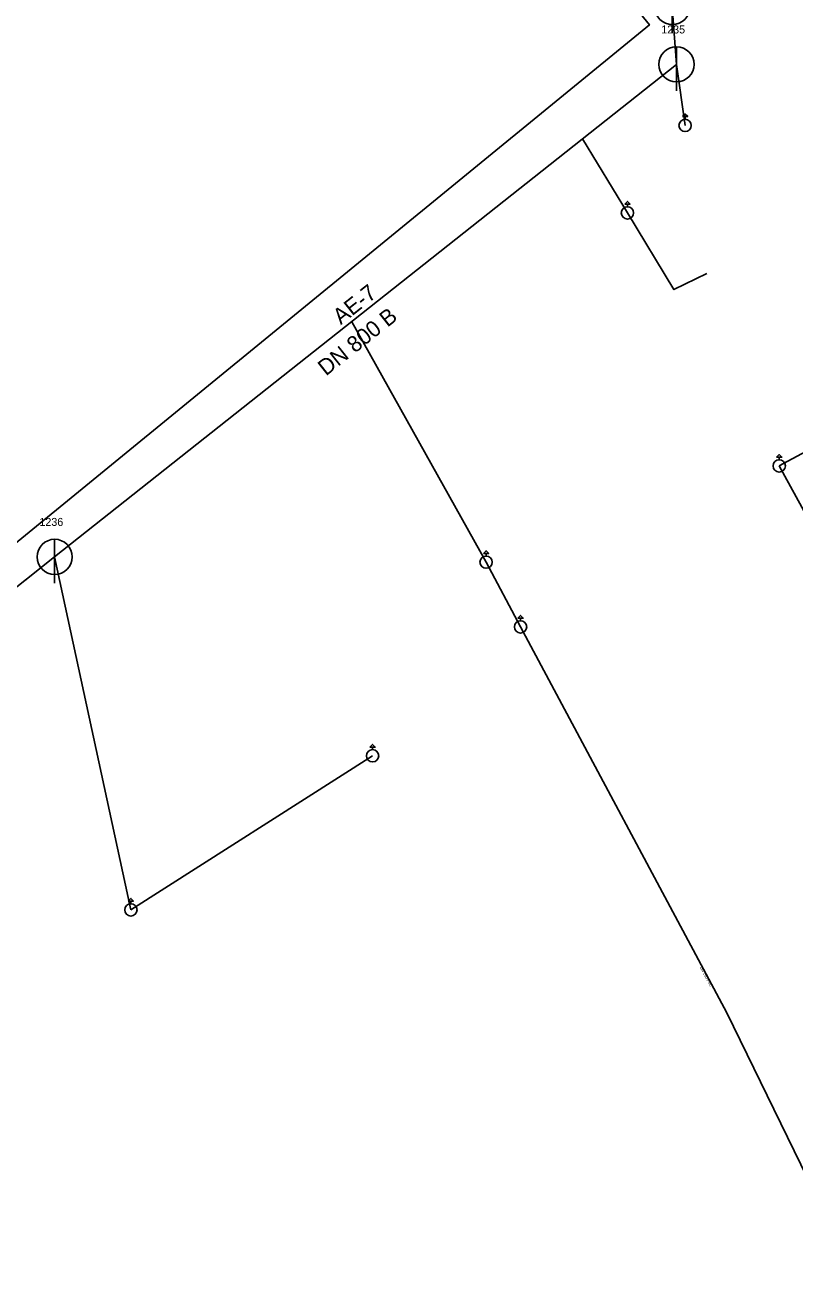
# Model space of a CAD drawing. Extents: x -493753 to -49291, y -1127285 to -112662.
# Drawn here: x -492986.6 to -492942.9, y -1126707.8 to -1126636.7 of the extents above; entities that cross this region are included whole.
import ezdxf

# ---------------------------------------------------------------- set-up
doc = ezdxf.new("R2010")
doc.units = 0
for name, color, linetype in [('Vrstva 1', 7, 'Continuous'), ('Vrstva 15', 7, 'Continuous'), ('Vrstva 17', 7, 'Continuous'), ('Vrstva 19', 7, 'Continuous')]:
    doc.layers.add(name, color=color, linetype=linetype)

# ---------------------------------------------------------------- blocks, each defined once
blk = doc.blocks.new('_SACHT')
at = {"layer": 'Vrstva 1'}
blk.add_line((0, 0.035), (0, 0.05), dxfattribs=at)
blk.add_lwpolyline([(-0.015, 0.05), (0, 0.065), (0.015, 0.05), (0.0025, 0.05)], close=True, dxfattribs=at)
blk.add_circle((0, 0), 0.035, dxfattribs=at)
blk = doc.blocks.new('_SACH0')
at = {"layer": 'Vrstva 1'}
blk.add_line((0, 0.05), (0, -0.075), dxfattribs=at)
blk.add_circle((0, 0), 0.05, dxfattribs=at)

msp = doc.modelspace()

# ---------------------------------------------------------------- linework, layer by layer
at = {"layer": 'Vrstva 15'}
for p, q in [((-492949.6, -1126638.98), (-492949.84, -1126635.71)), ((-492984.94, -1126666.98), (-492949.6, -1126638.98)), ((-492949.11, -1126642.45), (-492949.6, -1126638.98)), ((-492952.39, -1126647.42), (-492954.94, -1126643.21)), ((-492960.42, -1126667.28), (-492968.06, -1126653.61)), ((-492942.15, -1126664.75), (-492943.76, -1126661.81)), ((-493018.52, -1126693.58), (-492984.94, -1126666.98)), ((-492980.61, -1126687.05), (-492984.94, -1126666.98)), ((-492958.46, -1126670.96), (-492960.42, -1126667.28)), ((-492966.87, -1126678.29), (-492980.61, -1126687.05))]:
    msp.add_line(p, q, dxfattribs=at)
for points in [[(-493012.24, -1126645.18), (-492992.76, -1126670.76), (-492951.14, -1126636.73), (-492965.75, -1126618.81)], [(-492943.76, -1126661.81), (-492936.19, -1126657.72), (-492931.2, -1126655.03), (-492925.44, -1126645.32)], [(-492947.88, -1126650.86), (-492949.75, -1126651.78), (-492952.39, -1126647.42)], [(-492939.46, -1126707.81), (-492946.73, -1126692.9), (-492958.46, -1126670.96)]]:
    msp.add_lwpolyline(points, dxfattribs=at)

# ---------------------------------------------------------------- block references
at = {"layer": 'Vrstva 17'}
for name, p, xscale, yscale in [('_SACH0', (-492949.84, -1126635.71), 19.997500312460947, 19.997500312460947), ('_SACH0', (-492949.6, -1126638.98), 19.997500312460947, 19.997500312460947), ('_SACHT', (-492949.11, -1126642.45), 9.998750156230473, 9.998750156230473), ('_SACHT', (-492952.39, -1126647.42), 9.998750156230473, 9.998750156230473), ('_SACHT', (-492943.76, -1126661.81), 9.998750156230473, 9.998750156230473), ('_SACH0', (-492984.94, -1126666.98), 19.997500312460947, 19.997500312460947), ('_SACHT', (-492960.42, -1126667.28), 9.998750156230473, 9.998750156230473), ('_SACHT', (-492958.46, -1126670.96), 9.998750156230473, 9.998750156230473), ('_SACHT', (-492966.87, -1126678.29), 9.998750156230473, 9.998750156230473), ('_SACHT', (-492980.61, -1126687.05), 9.998750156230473, 9.998750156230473)]:
    msp.add_blockref(name, p, dxfattribs=dict(at, xscale=xscale, yscale=yscale))

# ---------------------------------------------------------------- texts
at = {"layer": 'Vrstva 19'}
for s, p in [('1235', (-492950.466, -1126637.22)), ('1236', (-492985.806, -1126665.22))]:
    msp.add_text(s, height=0.4549, dxfattribs=at).set_placement(p)
for s, height, rotation, p in [('AE-7', 0.9099, 38.38492, (-492968.677, -1126653.812)), ('DN 800 B', 0.9099, 38.38492, (-492969.524, -1126656.724)), ('DN 150 PVC', 0.1605, 298.12515, (-492948.285, -1126690.323))]:
    msp.add_text(s, height=height, rotation=rotation, dxfattribs=at).set_placement(p)

doc.saveas('drawing.dxf')
